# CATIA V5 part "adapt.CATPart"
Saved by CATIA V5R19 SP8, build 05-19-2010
Part number: adapt
Bounding box of the stored display mesh (mm): x -20 to 20, y 0 to 71.897, z -20 to 20
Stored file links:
  G:\EU_thinkMotion\CFAO_2010\SIL_groupe1\SIL_groupe1\A reprendre\fbruguiere\fbruguiere\fbruguiere\adapt.CATPart
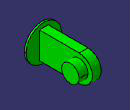
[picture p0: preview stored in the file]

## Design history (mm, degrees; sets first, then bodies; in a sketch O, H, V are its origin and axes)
Body1 (main body)
  Sketch1 on zx-plane, origin (0, 0, 0), H (-1, 0, 0), V (0, 0, 1)
    circle A1 centre (0, 0) radius 5.5
    point P1 (5.5, 0)
    radius A1 = 5.5
    coincidence: A1 P1, P1 H
  Pad1: profile Sketch1, direction (0, 1, 0), length 10
  Sketch2 on end face of Pad1, origin (0, 10, 0), H (-1, 0, 0), V (0, 0, 1)
    circle A1 centre (0, 0) radius 20
    radius A1 = 20
  Pad2: profile Sketch2, direction (0, 1, 0), length 2
  Sketch3 on end face of Pad2, origin (0, 12, 0), H (-1, 0, 0), V (0, 0, 1)
    line L1 (-5, 15) -> (5, 15)
    line L2 (5, 15) -> (5, -15)
    line L3 (5, -15) -> (-5, -15)
    line L4 (-5, -15) -> (-5, 15)
    reference intersected line E1 through (0, 0) direction (-1, 0) from xy-plane
    distance O L2 = 5
    distance L4 O = 5
    distance E1 L1 = 15
    distance L3 O = 15
    horizontal: L1 H, L3 H
    vertical: L2 V, L4 V
  Pad3: profile Sketch3, direction (0, 1, 0), length 60
  Sketch4 on face of Pad3 from Sketch3.L4, origin (5, 0, 0), H (0, 1, 0), V (0, 0, 1)
    arc A1 centre (56.9878, 0) radius 14.9096 from (56.9878, -14.9096) to (56.9878, 14.9096) ccw
    point P1 (56.9878, 0)
    line L1 (56.9878, 21.8345) -> (84.9262, 21.8345)
    line L2 (84.9262, 21.8345) -> (84.9262, -23.7622)
    line L3 (84.9262, -23.7622) -> (56.9878, -23.7622)
    line L4 (56.9878, -23.7622) -> (56.9878, -14.9096)
    line L5 (56.9878, 14.9096) -> (56.9878, 21.8345)
    coincidence: P1 H, L4 L5
    horizontal: L1 H, L3 H
    vertical: L2 V, L4 V, L5 V
  Pocket1: profile Sketch4, direction (-1, 0, 0), length 60
  Sketch5 on face of Pad3 from Sketch3.L4, origin (5, 0, 0), H (0, 1, 0), V (0, 0, 1)
    circle A1 centre (57, 0) radius 10
    point P1 (57, 0)
    reference projected line E1 (12, 15) -> (12, -15) from edge [end face of Pad2 | face of Pad3 from Sketch3.L4]
    radius A1 = 10
    distance P1 E1 = 45
    coincidence: P1 H
  Pad4: profile Sketch5, direction (1, 0, 0), length 10
  Sketch6 on end face of Pad2, origin (0, 12, 0), H (-1, 0, 0), V (0, 0, 1)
